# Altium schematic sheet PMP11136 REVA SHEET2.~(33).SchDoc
size 431 x 279 mm; Date: Not shown in title block; ApprovedBy: Not shown in title block; CheckedBy: Not shown in title block; Author: Not shown in title block; CompanyName: Not shown in title block; Engineer: Not shown in title block; Organization: Not shown in title block; Address1: Not shown in title block; Address2: Not shown in title block; Address3: Not shown in title block; Address4: Not shown in title block; DocumentNumber: 2; Revision: Use project parameter SCH_Rev; SheetNumber: 2; SheetTotal: 3; PageSetup: Record=PageOptions¦CenterHorizontal=True¦CenterVertical=True¦PrintScale=1.00¦XCorrection=1.00¦YCorrection=1.00¦PrintKind=0¦BorderSize=5000000¦LeftOffset=0¦BottomOffset=0¦Orientation=2¦PaperLength=1000¦PaperWidth=1000¦Scale=100¦PaperSource=15¦PrintQuality=600¦MediaType=1¦DitherType=10¦PaperKind=Letter¦PrintScaleMode=1
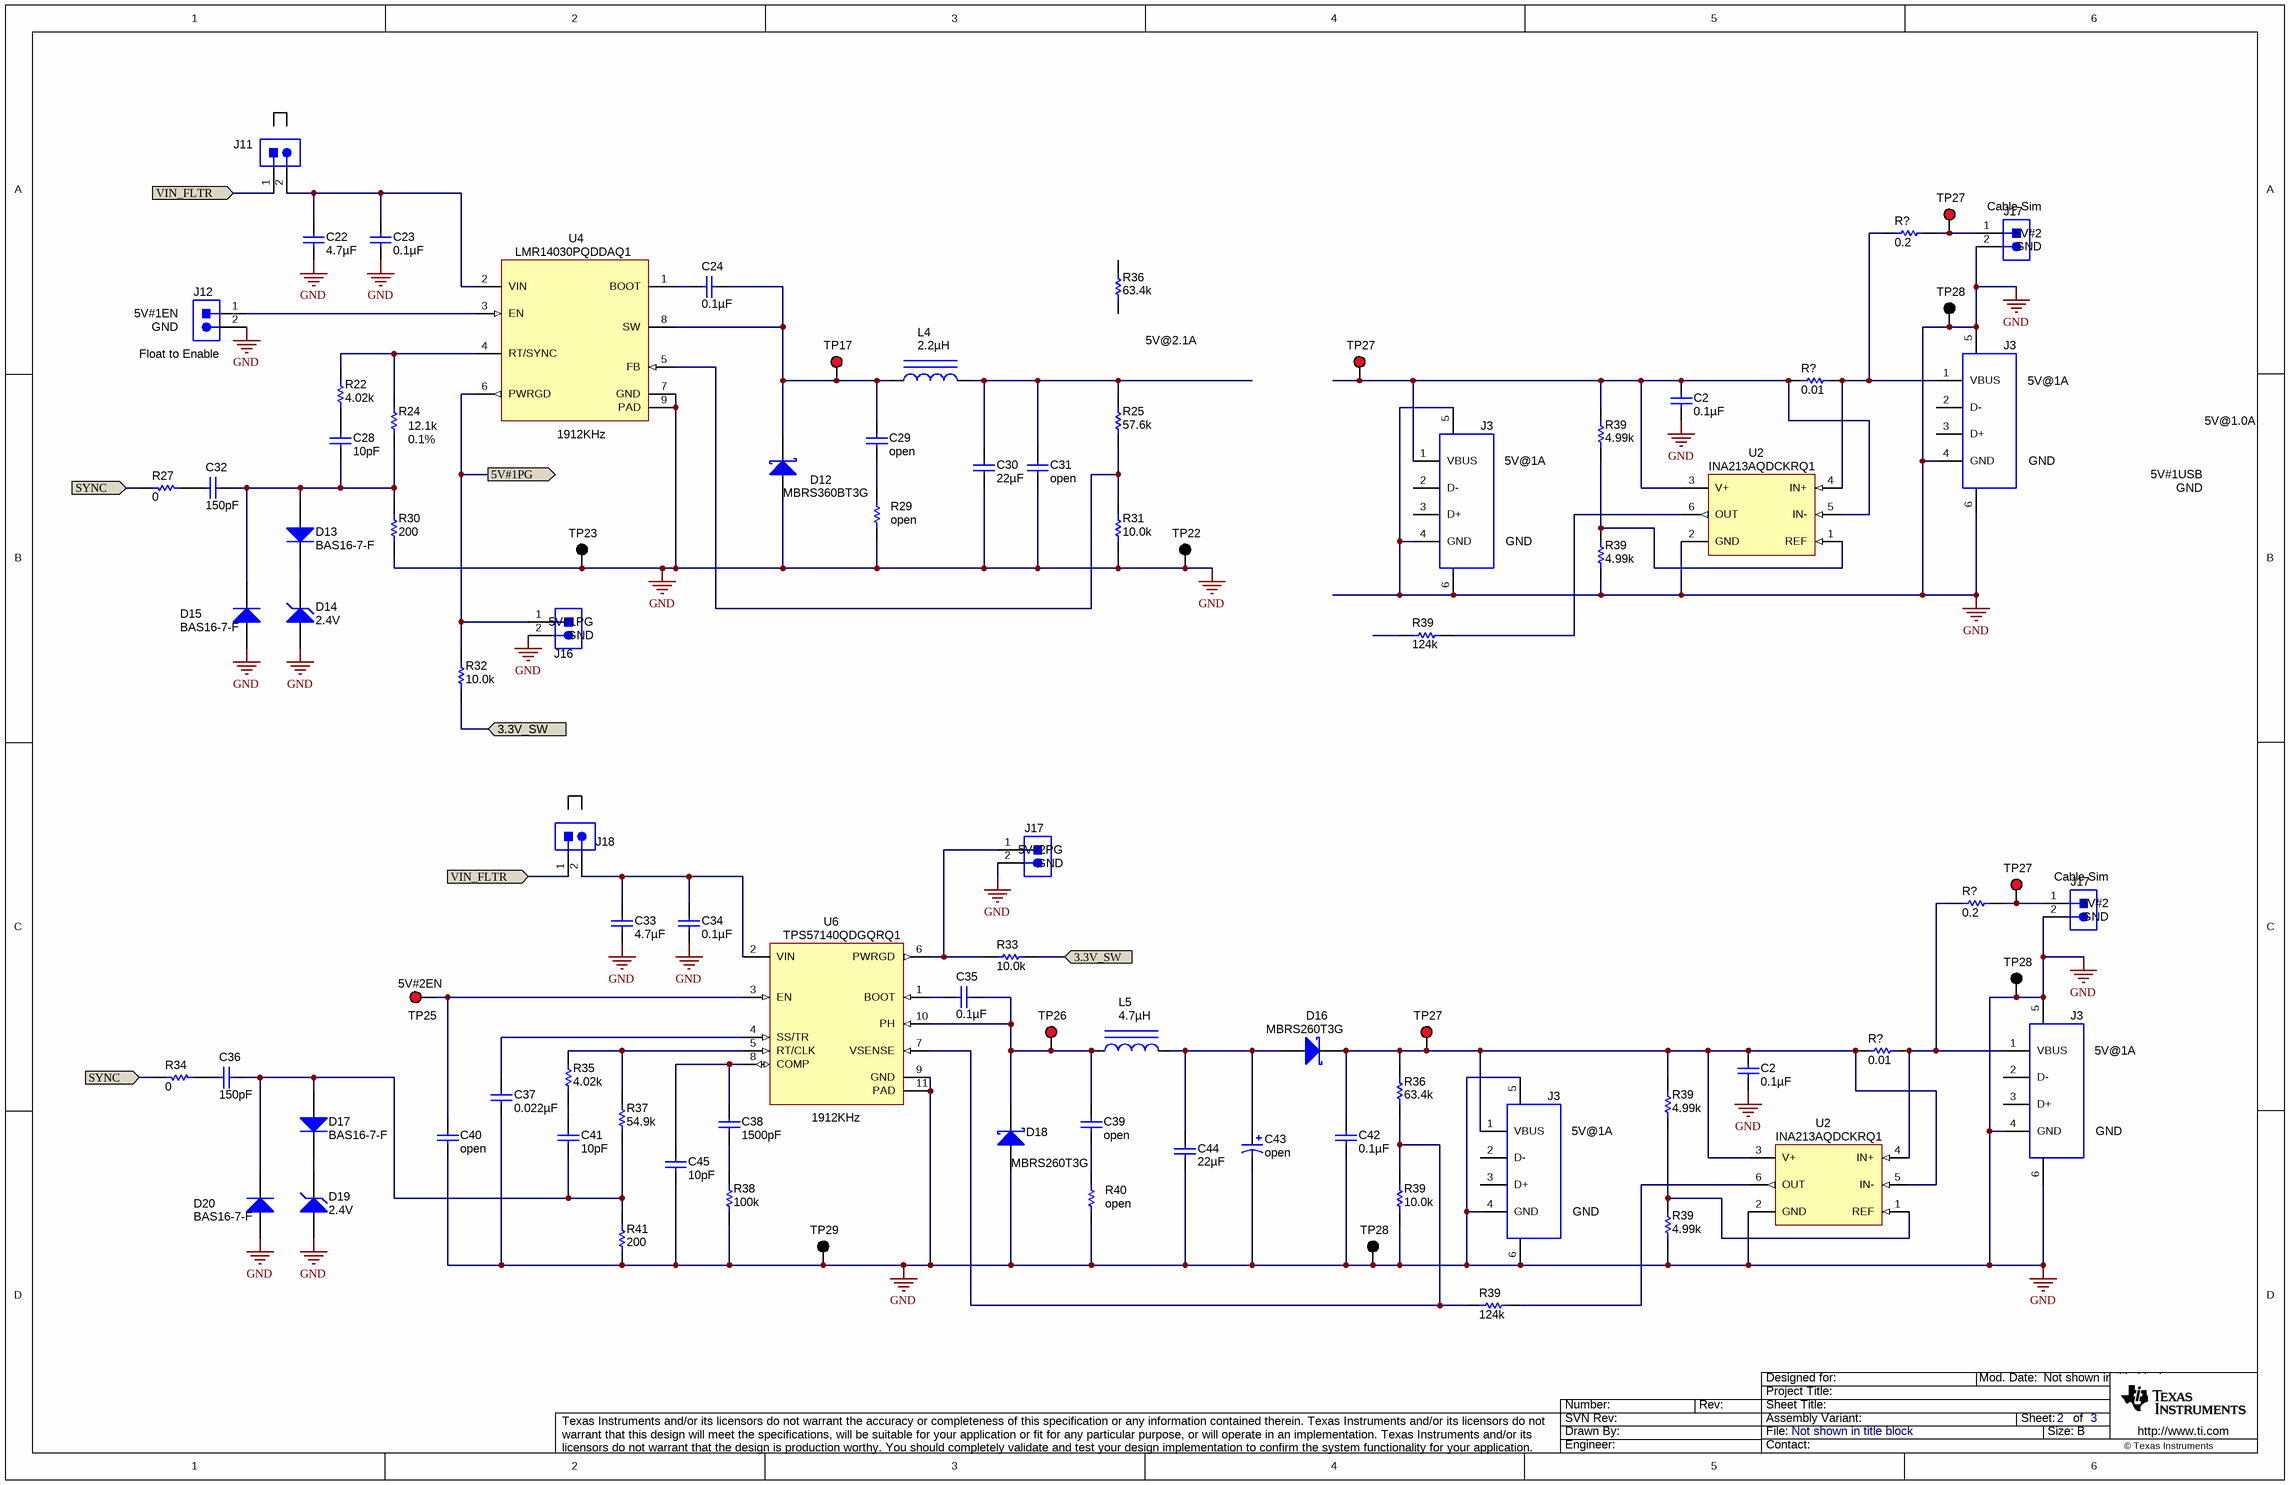
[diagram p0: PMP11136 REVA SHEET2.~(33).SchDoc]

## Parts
(Parts that share a designator on the sheet are numbered #1, #2 ... from top to bottom, then left to right.)
C2#1  ValueDisplayed: 0.1µF  [0402]  (hidden comment: C1005X7R1H104K050BB)
C2#2  ValueDisplayed: 0.1µF  [0402]  (hidden comment: C1005X7R1H104K050BB)
C22  ValueDisplayed: 4.7µF  [1210]  (hidden comment: C3225X7R1H475M250AB)
C23  ValueDisplayed: 0.1µF  [0603]  (hidden comment: C1608X7R1H104K)
C24  ValueDisplayed: 0.1µF  [0603]  (hidden comment: C1608X7R1H104K)
C28  ValueDisplayed: 10pF  [0603]  (hidden comment: C1608C0G1H100D)
C29  ValueDisplayed: open  [0603]
C30  ValueDisplayed: 22µF  [1210]  (hidden comment: C3225X7R1C226M250AC)
C31  ValueDisplayed: open  [1210]
C32  ValueDisplayed: 150pF  [0603]  (hidden comment: C1608C0G1H151J)
C33  ValueDisplayed: 4.7µF  [1210]  (hidden comment: C3225X7R1H475M250AB)
C34  ValueDisplayed: 0.1µF  [0603]  (hidden comment: C1608X7R1H104K)
C35  ValueDisplayed: 0.1µF  [0603]  (hidden comment: C1608X7R1H104K)
C36  ValueDisplayed: 150pF  [0603]  (hidden comment: C1608C0G1H151J)
C37  ValueDisplayed: 0.022µF  [0603]  (hidden comment: C1608X7R1H223K)
C38  ValueDisplayed: 1500pF  [0603]  (hidden comment: C1608C0G1H152J)
C39  ValueDisplayed: open  [0603]
C40  ValueDisplayed: open  [0603]
C41  ValueDisplayed: 10pF  [0603]  (hidden comment: C1608C0G1H100D)
C42  ValueDisplayed: 0.1µF  [0603]  (hidden comment: C1608X7R1H104K)
C43  ValueDisplayed: open  [TPB_D4]
C44  ValueDisplayed: 22µF  [1210]  (hidden comment: C3225X7R1C226M250AC)
C45  ValueDisplayed: 10pF  [0603]  (hidden comment: C1608C0G1H100D)
D12  MBRS360BT3G  [SMB]
D13  BAS16-7-F  [SOT-23]
D14  value 2.4V  [SOD-123]  (hidden comment: MMSZ5221B-7-F)
D15  BAS16-7-F  [SOT-23]
D16  MBRS260T3G  [SMB]
D17  BAS16-7-F  [SOT-23]
D18  MBRS260T3G  [SMB]
D19  value 2.4V  [SOD-123]  (hidden comment: MMSZ5221B-7-F)
D20  BAS16-7-F  [SOT-23]
J3#1  676430910  [MOLEX_0676430910]  (value not drawn)
J3#2  676430910  [MOLEX_0676430910]  (value not drawn)
J3#3  676430910  [MOLEX_0676430910]  (value not drawn)
J3#4  676430910  [MOLEX_0676430910]  (value not drawn)
J11  PEC02SAAN  [CONN_PEC02SAAN]  (value not drawn)
J12  PEC02SAAN  [CONN_PEC02SAAN]  (value not drawn)
J16  PEC02SAAN  [CONN_PEC02SAAN]  (value not drawn)
J17#1  PEC02SAAN  [CONN_PEC02SAAN]  (value not drawn)
J17#2  PEC02SAAN  [CONN_PEC02SAAN]  (value not drawn)
J17#3  PEC02SAAN  [CONN_PEC02SAAN]  (value not drawn)
J18  PEC02SAAN  [CONN_PEC02SAAN]  (value not drawn)
L4  ValueDisplayed: 2.2µH  [CLF6045NI-D]  (hidden comment: CLF6045NIT-2R2N-D)
L5  ValueDisplayed: 4.7µH  [CLF6045NI-D]  (hidden comment: CLF6045NIT-4R7N-D)
R22  ValueDisplayed: 4.02k  [0603]  (hidden comment: CRCW06034K02FKEA)
R24  Value1: 0.1%  ValueDisplayed: 12.1k  [0603]
R25  ValueDisplayed: 57.6k  [0603]  (hidden comment: CRCW060357K6FKEA)
R27  ValueDisplayed: 0  [0603]  (hidden comment: CRCW06030000Z0EA)
R29  value open  [2010]
R30  ValueDisplayed: 200  [0603]  (hidden comment: CRCW0603200RFKEA)
R31  ValueDisplayed: 10.0k  [0603]  (hidden comment: CRCW060310K0FKEA)
R32  ValueDisplayed: 10.0k  [0603]  (hidden comment: CRCW060310K0FKEA)
R33  ValueDisplayed: 10.0k  [0603]  (hidden comment: CRCW060310K0FKEA)
R34  ValueDisplayed: 0  [0603]  (hidden comment: CRCW06030000Z0EA)
R35  ValueDisplayed: 4.02k  [0603]  (hidden comment: CRCW06034K02FKEA)
R36#1  ValueDisplayed: 63.4k  [0603]  (hidden comment: CRCW060363K4FKEA)
R36#2  ValueDisplayed: 63.4k  [0603]  (hidden comment: CRCW060363K4FKEA)
R37  ValueDisplayed: 54.9k  [0603]  (hidden comment: CRCW060354K9FKEA)
R38  ValueDisplayed: 100k  [0603]  (hidden comment: CRCW0603100KFKEA)
R39#1  ValueDisplayed: 4.99k  [0603]  (hidden comment: CRCW06034K99FKEA)
R39#2  ValueDisplayed: 4.99k  [0603]  (hidden comment: CRCW06034K99FKEA)
R39#3  ValueDisplayed: 124k  [0603]  (hidden comment: CRCW0603124KFKEA)
R39#4  ValueDisplayed: 4.99k  [0603]  (hidden comment: CRCW06034K99FKEA)
R39#5  ValueDisplayed: 10.0k  [0603]  (hidden comment: CRCW060310K0FKEA)
R39#6  ValueDisplayed: 4.99k  [0603]  (hidden comment: CRCW06034K99FKEA)
R39#7  ValueDisplayed: 124k  [0603]  (hidden comment: CRCW0603124KFKEA)
R40  value open  [2010]
R41  ValueDisplayed: 200  [0603]  (hidden comment: CRCW0603200RFKEA)
R?#1  ValueDisplayed: 0.2  [2512]  (hidden comment: CSRN2512FKR200)
R?#2  ValueDisplayed: 0.01  [1206]  (hidden comment: CSR1206FK10L0)
R?#3  ValueDisplayed: 0.2  [2512]  (hidden comment: CSRN2512FKR200)
R?#4  ValueDisplayed: 0.01  [1206]  (hidden comment: CSR1206FK10L0)
TP17  5000  [Keystone5000]  (value not drawn)
TP22  5001  [Keystone5001]  (value not drawn)
TP23  5001  [Keystone5001]  (value not drawn)
TP25  5000  [Keystone5000]  (value not drawn)
TP26  5000  [Keystone5000]  (value not drawn)
TP27#1  5000  [Keystone5000]  (value not drawn)
TP27#2  5000  [Keystone5000]  (value not drawn)
TP27#3  5000  [Keystone5000]  (value not drawn)
TP27#4  5000  [Keystone5000]  (value not drawn)
TP28#1  5001  [Keystone5001]  (value not drawn)
TP28#2  5001  [Keystone5001]  (value not drawn)
TP28#3  5001  [Keystone5001]  (value not drawn)
TP29  5001  [Keystone5001]  (value not drawn)
U2#1  INA213AQDCKRQ1  [DCK0006A_N]
U2#2  INA213AQDCKRQ1  [DCK0006A_N]
U4  LMR14030PQDDAQ1  [DDA0008E_N]
U6  TPS57140QDGQRQ1  [DGQ0010D_N]

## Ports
3.3V_SW, 5V#1PG, SYNC, VIN_FLTR

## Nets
GND: C2#1.2 C2#2.2 C22.1 C23.2 C30.2 C31.2 C33.1 C34.2 C37.2 C40.2 C42.2 C43.2(-) C44.2 C45.2 D12.2(A) D14.2(A) D15.1(A) D18.2(A) D19.2(A) D20.1(A) J3#1.4(GND) J3#1.5(Shield) J3#1.6(Shield) J3#2.4(GND) J3#2.5(Shield) J3#2.6(Shield) J3#3.4(GND) J3#3.5(Shield) J3#3.6(Shield) J3#4.4(GND) J3#4.5(Shield) J3#4.6(Shield) J12.2 J16.2 J17#1.2 J17#2.2 J17#3.2 R29.1 R30.1 R31.1 R38.1 R39#2.2 R39#5.1 R39#6.2 R40.1 R41.1 TP22.1 TP23.1 TP28#1.1 TP28#2.1 TP28#3.1 TP29.1 U2#1.2(GND) U2#2.2(GND) U4.7(GND) U4.9(PAD) U6.9(GND) U6.11(PAD)
3.3V_SW: R32.1 R33.1 ; port 3.3V_SW
5V#1PG: J16.1 R32.2 U4.6(PWRGD) ; port 5V#1PG
SYNC: R27.1 R34.1 ; port SYNC
VIN_FLTR: J11.1 J18.1 ; port VIN_FLTR
NetC2#1_1: C2#1.1 J3#2.1(VBUS) R39#1.1 R?#2.1 TP27#2.1 U2#1.3(V+) U2#1.5(IN-)
NetC2#2_1: C2#2.1 C42.1 D16.1(K) J3#4.1(VBUS) R36#2.2 R39#4.1 R?#4.1 TP27#4.1 U2#2.3(V+) U2#2.5(IN-)
NetC22_2: C22.2 C23.1 J11.2 U4.2(VIN)
NetC24_1: C24.1 U4.1(BOOT)
NetC24_2: C24.2 C29.1 D12.1(K) L4.1 TP17.1 U4.8(SW)
NetC28_1: C28.1 R22.2
NetC28_2: C28.2 C32.1 D13.1(A) D15.3(K) R24.1 R30.2
NetC29_2: C29.2 R29.2
NetC30_1: C30.1 C31.1 L4.2 R25.2
NetC32_2: C32.2 R27.2
NetC33_2: C33.2 C34.1 J18.2 U6.2(VIN)
NetC35_1: C35.1 U6.1(BOOT)
NetC35_2: C35.2 C39.1 D18.1(K) L5.1 TP26.1 U6.10(PH)
NetC36_1: C36.1 C41.2 D17.1(A) D20.3(K) R37.1 R41.2
NetC36_2: C36.2 R34.2
NetC37_1: C37.1 U6.4(SS/TR)
NetC38_1: C38.1 C45.1 U6.8(COMP)
NetC38_2: C38.2 R38.2
NetC39_2: C39.2 R40.2
NetC40_1: C40.1 TP25.1 U6.3(EN)
NetC41_1: C41.1 R35.2
NetC43_1: C43.1(+) C44.1 D16.2(A) L5.2
NetD13_3: D13.3(K) D14.1(K)
NetD17_3: D17.3(K) D19.1(K)
NetJ3#1_1: J3#1.1(VBUS) R?#1.1 R?#2.2 U2#1.4(IN+)
NetJ3#3_1: J3#3.1(VBUS) R?#3.1 R?#4.2 U2#2.4(IN+)
NetJ12_1: J12.1 U4.3(EN)
NetJ17#1_1: J17#1.1 R?#1.2 TP27#1.1
NetJ17#2_1: J17#2.1 R33.2 U6.6(PWRGD)
NetJ17#3_1: J17#3.1 R?#3.2 TP27#3.1
NetR22_1: R22.1 R24.2 U4.4(RT/SYNC)
NetR25_1: R25.1 R31.2 U4.5(FB)
NetR35_1: R35.1 R37.2 U6.5(RT/CLK)
NetR36#2_1: R36#2.1 R39#5.2 R39#7.2 U6.7(VSENSE)
NetR39#1_2: R39#1.2 R39#2.1 U2#1.1(REF)
NetR39#3_1: R39#3.1 U2#1.6(OUT)
NetR39#4_2: R39#4.2 R39#6.1 U2#2.1(REF)
NetR39#7_1: R39#7.1 U2#2.6(OUT)

Not connected (* = marked no-connect by the designer): J3#1 2(D-) 3(D+); J3#2 2(D-) 3(D+); J3#3 2(D-) 3(D+); J3#4 2(D-) 3(D+); R36#1 1 2; R39#3 2

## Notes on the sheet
- (near J17#1) 5V#2
- (near J17#1) Cable Sim
- (near J17#1) GND
- (near J12) 5V#1EN
- (near J12) GND
- (near J12) Float to Enable
- 5V@2.1A
- (near U4) 1912KHz
- 5V@1A
- 5V@1.0A
- GND
- 5V#1USB
- 5V#1PG
- (near J16) GND
- (near J17#2) 5V#2PG
- (near J17#2) GND
- (near J17#3) 5V#2
- (near J17#3) Cable Sim
- (near J17#3) GND
- (near TP25) 5V#2EN
- (near U6) 1912KHz

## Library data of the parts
C2#1 C2#2 = C1005X7R1H104K050BB: CAP, CERM, 0.1uF, 50V, +/-10%, X7R, 0402; Manufacturer: TDK; Polarized: N; CompType: Capacitor; U/M: EA; Cap_F: 0.0000001; Tolerance_%: 10; Value1: Unknown; VDC_V: 50; TaMin_C: -55; TaMax_C: 125
C22 C33 = C3225X7R1E106M: CAP, CERM, 4.7uF, 50V, +/-20%, X7R, 1210; Manufacturer: TDK; Polarized: N; CompType: Capacitor; U/M: EA; Cap_F: 0.00001; Tolerance_%: 20; ESR_Ohm: 0.0027; Value1: 0.0027 ohm; VDC_V: 50; IRMS_A: 3; TaMin_C: -55; TaMax_C: 125
C23 C24 C34 C35 C42 = C1608X7R1H104K: CAP, CERM, 0.1uF, 50V, +/-10%, X7R, 0603; Manufacturer: TDK; Polarized: N; CompType: Capacitor; U/M: EA; Cap_F: 0.0000001; Tolerance_%: 10; ESR_Ohm: 0.017; Value1: 0.017 ohm; VDC_V: 50; TaMin_C: -55; TaMax_C: 125
C28 C41 C45 = C1608C0G1H100D: CAP, CERM, 10 pF, 50 V, +/- 5%, C0G/NP0, 0603; Manufacturer: TDK; Polarized: N; CompType: Capacitor; Value: 10pF; U/M: EA; Cap_F: 0.00000000001; Tolerance_%: 5; ESR_ohm: 0.3492; Value1: 0.3492 ohm; VDC_V: 50; Value2: 50V; TaMin_C: -55; TaMax_C: 125
C29 C39 C40 = C1608C0G1H102J: CAP, CERM, open, 0603; Polarized: N; CompType: Capacitor; U/M: EA; Cap_F: 0.000000001; Tolerance_%: 5; ESR_ohm: 0.0563; TempCo: C0G/NP0; TaMin_C: -55; TaMax_C: 125
C30 C44 = C3225X7R1C226M: CAP, CERM, 22 µF, 16 V, +/- 20%, X7R, 1210; Manufacturer: TDK; Polarized: N; CompType: Capacitor; Value: 22uF; U/M: EA; Cap_F: 0.000022; Tolerance_%: 20; ESR_ohm: 0.002; Value1: 0.002 ohm; VDC_V: 16; Value2: 16V; IRMS_A: 8.11; TaMin_C: -55; TaMax_C: 125
C31 = C3225X7R1C226M: CAP, open, 1210; Polarized: N; CompType: Capacitor; U/M: EA; Cap_F: 0.000022; Tolerance_%: 20; ESR_ohm: 0.002; TempCo: X7R; IRMS_A: 8.11; TaMin_C: -55; TaMax_C: 125
C32 C36 = C1608C0G1H151J: CAP, CERM, 150 pF, 50 V, +/- 5%, C0G/NP0, 0603; Manufacturer: TDK; Polarized: N; CompType: Capacitor; Value: 150pF; U/M: EA; Cap_F: 0.00000000015; Tolerance_%: 5; ESR_ohm: 0.1084; Value1: 0.1084 ohm; VDC_V: 50; Value2: 50V; TaMin_C: -55; TaMax_C: 125
C37 = C1608X7R1H223K: CAP, CERM, 0.022 µF, 50 V, +/- 10%, X7R, 0603; Manufacturer: TDK; Polarized: N; CompType: Capacitor; Value: 0.022uF; U/M: EA; Cap_F: 0.000000022; Tolerance_%: 10; ESR_ohm: 0.0383; Value1: 0.0383 ohm; VDC_V: 50; Value2: 50V; TaMin_C: -55; TaMax_C: 125
C38 = C1608C0G1H152J: CAP, CERM, 1500 pF, 50 V, +/- 5%, C0G/NP0, 0603; Manufacturer: TDK; Polarized: N; CompType: Capacitor; Value: 1500pF; U/M: EA; Cap_F: 0.0000000015; Tolerance_%: 5; ESR_ohm: 0.039; Value1: 0.039 ohm; VDC_V: 50; Value2: 50V; TaMin_C: -55; TaMax_C: 125
C43 = 10TPB220M: CAP, open, SMD; Polarized: Y; CompType: Capacitor; Value: 150uF; U/M: EA; Cap_F: 0.00022; Tolerance_%: 20; ESR_Ohm: 0.04; IRMS_A: 3; TaMin_C: -55; TaMax_C: 105; Cap_Case: D
D12 = MBRS260T3G: Diode, Schottky, 60V, 3A, SMB; Manufacturer: ON Semiconductor; U/M: EA; Vf_V: 0.63; Value2: 0.63V; Io_A: 2; Vr_V: 60; TJmax_C: 125; RJC_CperW: 24
D13 D15 D17 D20 = BAS16-7-F: Diode, Ultrafast, 75V, 0.3A, SOT-23; Manufacturer: Diodes Inc.; U/M: EA; Vf_V: 1.125; Value2: 1.125V; Io_A: 0.3; Vr_V: 75
D14 D19 = MMSZ5221B-7-F: Diode, Zener, 2.4V, 500 mW, SOD-123; Manufacturer: Diodes Inc.; SymbolCreator: a0412235; U/M: EA; Power_W: 0.5; Vz_V: 2.4; Value1: 0.5W; RJA_CperW: 350
D16 D18 = MBRS260T3G: Diode, Schottky, 60V, 2A, SMB; Manufacturer: ON Semiconductor; U/M: EA; Vf_V: 0.63; Value2: 0.63V; Io_A: 2; Vr_V: 60; TJmax_C: 125; RJC_CperW: 24
J3#1-J3#4 = 676430910: Connector, Receptacle, USB Standard, R/A, Top Mount TH; Manufacturer: Molex; SymbolCreator: a0412235; U/M: EA
J11 J12 J16 J17#1-J17#3 J18 = PEC02SAAN: Header, 100mil, 2x1, Tin, TH; Manufacturer: Sullins Connector Solutions; SymbolCreator: a0412235; U/M: EA
L4 = CLF6045NIT-2R2N-D: Inductor, Wirewound, Ferrite, 2.2 µH, 4.1 A, 0.015 ohm, SMD; Manufacturer: TDK; Value: 2.2uH; Ind_H: 2.2E-6; Imax_A: 4.1; Irms: 4.1A @ 40C rise; Isat: 4.2A @ 30% inductance drop; DCR_ohm: 0.015; Value2: 4.1A
L5 = CLF6045NIT-4R7N-D: Inductor, Wirewound, Ferrite, 4.7 µH, 3.1 A, 0.023 ohm, SMD; Manufacturer: TDK; Value: 4.7uH; Ind_H: 4.7E-6; Imax_A: 3.1; Irms: 3.3A @ 40C rise; Isat: 3.1A @ 30% inductance drop; DCR_ohm: 0.023; Value2: 3.1A
R22 R35 = CRCW06034K02FKEA: RES, 4.02 k, 1%, 0.1 W, 0603; Manufacturer: Vishay-Dale; CompType: Resistor; Value: 4.02k; Res_ohm: 4020; Value_Code: 4k02; Tolerance_%: 1; Power_W: 0.1; Value2: 0.1W; VDC_V: 75; TempCo: 100 ppm/C; EIA_Code: E96; U/M: EA
R24 = CRCW060312K1FKEA: RES, 12.1 k, 0.1%, 0.1 W, 0603; Manufacturer: Vishay-Dale; CompType: Resistor; Value: 12.1k; Res_ohm: 12100; Value_Code: 12k1; Tolerance_%: 1; Power_W: 0.1; Value2: 0.1W; VDC_V: 75; TempCo: 100 ppm/C; EIA_Code: E96; U/M: EA
R25 = CRCW060357K6FKEA: RES, 57.6 k, 1%, 0.1 W, 0603; Manufacturer: Vishay-Dale; CompType: Resistor; Value: 57.6k; Res_ohm: 57600; Value_Code: 57k6; Tolerance_%: 1; Power_W: 0.1; Value2: 0.1W; VDC_V: 75; TempCo: 100 ppm/C; EIA_Code: E96; U/M: EA
R27 R34 = CRCW06030000Z0EA: RES, 0, 5%, 0.1 W, 0603; Manufacturer: Vishay-Dale; CompType: Resistor; Value: 0; Value_Code: 0000; Tolerance_%: 5; Power_W: 0.1; Value2: 0.1W; VDC_V: 75; TempCo: 200 ppm/C; EIA_Code: E24; U/M: EA
R29 R40 = CRCW20102R70JNEF: RES, open, 2010; CompType: Resistor; Tolerance_%: 5; Power_W: 0.75; TempCo: 200 ppm/C; EIA_Code: E24; U/M: EA
R30 R41 = CRCW0603200RFKEA: RES, 200, 1%, 0.1 W, 0603; Manufacturer: Vishay-Dale; CompType: Resistor; Value: 200; Value_Code: 200R; Tolerance_%: 1; Power_W: 0.1; Value2: 0.1W; VDC_V: 75; TempCo: 100 ppm/C; EIA_Code: E96; U/M: EA
R31-R33 R39#5 = CRCW060310K0FKEA: RES, 10.0 k, 1%, 0.1 W, 0603; Manufacturer: Vishay-Dale; CompType: Resistor; Value: 10.0k; Res_ohm: 10000; Value_Code: 10k0; Tolerance_%: 1; Power_W: 0.1; Value2: 0.1W; VDC_V: 75; TempCo: 100 ppm/C; EIA_Code: E96; U/M: EA
R36#1 R36#2 = CRCW060363K4FKEA: RES, 63.4 k, 1%, 0.1 W, 0603; Manufacturer: Vishay-Dale; CompType: Resistor; Value: 63.4k; Res_ohm: 63400; Value_Code: 63k4; Tolerance_%: 1; Power_W: 0.1; Value2: 0.1W; VDC_V: 75; TempCo: 100 ppm/C; EIA_Code: E96; U/M: EA
R37 = CRCW060354K9FKEA: RES, 54.9 k, 1%, 0.1 W, 0603; Manufacturer: Vishay-Dale; CompType: Resistor; Value: 54.9k; Res_ohm: 54900; Value_Code: 54k9; Tolerance_%: 1; Power_W: 0.1; Value2: 0.1W; VDC_V: 75; TempCo: 100 ppm/C; EIA_Code: E96; U/M: EA
R38 = CRCW0603100KFKEA: RES, 100 k, 1%, 0.1 W, 0603; Manufacturer: Vishay-Dale; CompType: Resistor; Value: 100k; Res_ohm: 100000; Tolerance_%: 1; Power_W: 0.1; Value2: 0.1W; VDC_V: 75; TempCo: 100 ppm/C; EIA_Code: E96; U/M: EA
R39#1 R39#2 R39#4 R39#6 = CRCW06034K99FKEA: RES, 4.99 k, 1%, 0.1 W, 0603; Manufacturer: Vishay-Dale; CompType: Resistor; Value: 4.99k; Res_ohm: 4990; Value_Code: 4k99; Tolerance_%: 1; Power_W: 0.1; Value2: 0.1W; VDC_V: 75; TempCo: 100 ppm/C; EIA_Code: E96; U/M: EA
R39#3 R39#7 = CRCW0603124KFKEA: RES, 124 k, 1%, 0.1 W, 0603; Manufacturer: Vishay-Dale; CompType: Resistor; Value: 124k; Res_ohm: 124000; Tolerance_%: 1; Power_W: 0.1; Value2: 0.1W; VDC_V: 75; TempCo: 100 ppm/C; EIA_Code: E96; U/M: EA
R?#1 R?#3 = CSRN2512FKR200: RES, 0.2, 1%, 2 W, 2512; Manufacturer: Stackpole Electronics Inc; CompType: Resistor; Value: 0.2; Value_Code: R200; Tolerance_%: 1; Power_W: 2; Value2: 2W; TempCo: 200 ppm/C; EIA_Code: E96; U/M: EA
R?#2 R?#4 = CSR1206FK10L0: RES, 0.01, 1%, 0.5 W, 1206; Manufacturer: Stackpole Electronics Inc; CompType: Resistor; Value: 0.01; Value_Code: R010; Tolerance_%: 1; Power_W: 0.5; Value2: 0.5W; TempCo: 100 ppm/C; EIA_Code: E96; U/M: EA
TP17 TP25 TP26 TP27#1-TP27#4 = 5000: Test Point, TH, Miniature, Red; Manufacturer: Keystone; CompType: Test Point Loop; U/M: EA
TP22 TP23 TP28#1-TP28#3 TP29 = 5001: Test Point, TH, Miniature, Black; Manufacturer: Keystone; CompType: Test Point Loop; U/M: EA
U2#1 U2#2 = INA213AIDCK: Voltage Output, High or Low Side Measurement, Bi-Directional Zero-Drift Series Current-Shunt Monitor, DCK0006A; Alternate Manufacturer: None; Manufacturer: Texas Instruments; SymbolCreator: a0411947; CompType: IC; U/M: EA
U4 = LMR14030PDDAR: LMR14030PQDDAQ1, DDA0008E; Manufacturer: Texas Instruments; SymbolCreator: Altium; CompType: IC; U/M: EA
U6 = TPS57140QDGQRQ1: 1.5-A 42-V STEP-DOWN SWIFT(TM) DC-DC CONVERTER WITH Eco-mode(TM) CONTROL, DGQ0010D; Alternate Manufacturer: None; Manufacturer: Texas Instruments; SymbolCreator: a0799628; CompType: IC; U/M: EA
